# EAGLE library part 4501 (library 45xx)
NAND/NOR/OR
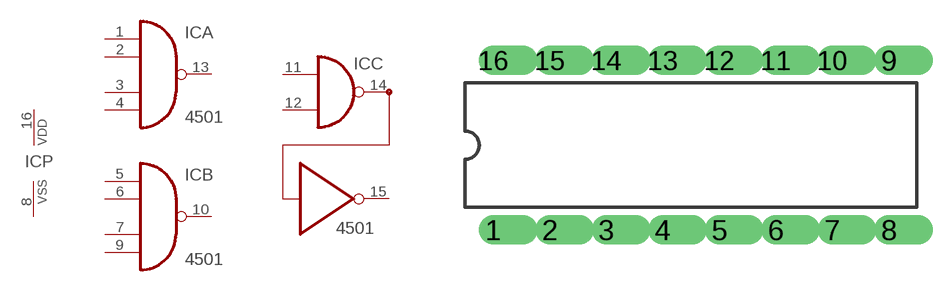
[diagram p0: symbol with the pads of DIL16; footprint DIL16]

Designator prefix IC; gates A=4501 B=4501 C=4501/A P=PWRN

## 4501N  [DIL16]
1  A:I0  in
2  A:I1  in
3  A:I2  in
4  A:I3  in
5  B:I0  in
6  B:I1  in
7  B:I2  in
8  P:VSS  pwr
9  B:I3  in
10  B:O  out
11  C:I0  in
12  C:I1  in
13  A:O  out
14  C:O1  out
15  C:O2  out
16  P:VDD  pwr

## Footprint DIL16 (pad centres in mm)
Dual In Line
drill 0.813 offset: 1 -8.89,-3.81; 2 -6.35,-3.81; 3 -3.81,-3.81; 4 -1.27,-3.81; 5 1.27,-3.81; 6 3.81,-3.81; 7 6.35,-3.81; 8 8.89,-3.81; 9 8.89,3.81; 10 6.35,3.81; 11 3.81,3.81; 12 1.27,3.81; 13 -1.27,3.81; 14 -3.81,3.81; 15 -6.35,3.81; 16 -8.89,3.81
